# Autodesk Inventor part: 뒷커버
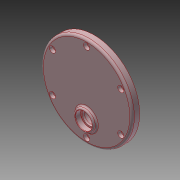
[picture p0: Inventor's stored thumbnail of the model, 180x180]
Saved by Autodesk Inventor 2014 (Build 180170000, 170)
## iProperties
Created: 2024-02
Part Number: 뒷커버
Material: 알루미늄 6061
Document SubType Name: Modeling
Designer: mdu-01
Density: 2.71 g/cm^3
Mass: 304.885 g
Surface Area: 294.624 cm^2
Volume: 112.504 cm^3
Appearance: 기본값(1)
Author: mdu-01
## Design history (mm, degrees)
sketch "스케치1"
  geometry: C1 r 60 at (0, 0) reference; C2 r 44 at (0, 0) reference; C3 r 11 at (0, -31) reference; C4 r 11 at (0, 0) reference; C5 r 46 at (0, 0) reference; A1 r 41 centre (0, 0) between (20.39, -35.57) and (-20.39, -35.57); A2 r 16 centre (0, 0) between (9.254, -13.053) and (-9.254, -13.053); A3 r 16 centre (0, -31) between (15.914, -32.657) and (9.254, -17.947); A4 r 16 centre (0, -31) between (-9.254, -17.947) and (-15.914, -32.657); A5 r 3 centre (18.898, -32.968) between (15.914, -32.657) and (20.39, -35.57); A6 r 3 centre (-18.898, -32.968) between (-20.39, -35.57) and (-15.914, -32.657); A7 r 3 centre (-10.989, -15.5) between (-9.254, -17.947) and (-9.254, -13.053); A8 r 3 centre (10.989, -15.5) between (9.254, -13.053) and (9.254, -17.947); 1 further point
  constraints: 16 point on circle, 8 centre point, 8 tangent, 5 equal radius
  dimensions: "d2" = 5 radial gap between concentric circles of C4 A2; "d3" = 3 radius of A5; "d46" = 5 radial gap between concentric circles of C5 A1
  node "참조1"
  node "참조2"
  node "참조3"
  node "참조4"
  node "참조11"
extrude "돌출1" new body sketch "스케치1" distance "d4" = 10; taper "d5" = 0 deg
extrude "돌출2" join sketch "스케치1" distance "d6" = 3; taper "d7" = 0 deg
chamfer "모따기1" distance "d8" = 1; stored, may be unused: second distance "d9" = 2, angle "d10" = 45 deg
sketch "스케치2"
  geometry: C1 r 13.5 at (0, -31); A1 r 3.5 centre (0, -31) between (1, -34.354) and (-1, -34.354) reference; 1 further point
  constraints: 1 centre point
  dimensions: "d11" = 27 diameter of C1
extrude "돌출3" join sketch "스케치2" distance "d14" = 4; taper "d15" = 0 deg
fillet "모깎기1" dims "d16" = 3
sketch "스케치3"
  geometry: C1 r 1.621 at (0, 52) reference; 1 further point
hole "구멍1" sketch "스케치3" at (0, 52) diameter "d18" = 4.5; stored, may be unused: countersink angle "d22" = 90 deg, drill point angle "d24" = 118 deg; dims "d19" = 6, "d20" = 8, "d21" = 4.4, "d23" = 8
fillet "모깎기2" dims "d31" = 2
sketch "스케치4"
  geometry: L1 (11, 3.7)-(11, -2.7) reference; L2 (-10.7, 4)-(10.7, 4) reference; L3 (10.7, -3)-(-10.7, -3) reference; L4 (10.7, -3)-(11, -3); L5 (11, -3)-(11, -2.7); L6 (6, 7)-(0, 7); L7 (0, 7)-(0, -3); L8 (10.7, 4)-(9, 4); A1 r 0.3 centre (10.7, 3.7) between (11, 3.7) and (10.7, 4); A2 r 3 centre (6, 4) between (9, 4) and (6, 7); 1 further point
  constraints: 13 end point, 4 point on circle, 3 tangent, 2 centre point, 2 collinear, 2 perpendicular, 2 point on line, 1 midpoint, 1 vertical, 2 other
  dimensions: "d33" = 3 distance from line of L6.start L2; "d34" = 2 distance from line of L8.end L1
revolve "회전1" sketch "스케치4" stored, may be unused: angle "d35" = 90 deg
sketch "스케치5"
  geometry: L1 (-20.3, -3)-(-41.7, -3) reference; L2 (-20, 3.7)-(-20, -2.7) reference; L3 (-41.7, 4)-(-20.3, 4) reference; L4 (-42.5, 14)-(-19.5, 14) reference; L5 (-20.3, -3)-(-20, -3); L6 (-20, -3)-(-20, -2.7); L7 (-20.3, 4)-(-22, 4); L8 (-20, 13.3)-(-20, 7); L9 (-20.3, 6.7)-(-22, 6.7); L10 (-22, 6.7)-(-22, 4); L11 (-19.596, 14)-(-20, 13.3); L12 (-31, -3)-(-31, 14); A1 r 0.3 centre (-20.3, 3.7) between (-20, 3.7) and (-20.3, 4); A2 r 0.3 centre (-20.3, 7) between (-20.3, 6.7) and (-20, 7); 1 further point
  constraints: 18 end point, 4 point on circle, 3 perpendicular, 3 tangent, 2 centre point, 2 midpoint, 2 parallel, 2 point on line, 1 vertical, 2 other
  dimensions: "d36" = 7.3 distance between parallel lines of L9 L4; "d37" = 2 distance between parallel lines of L2 L10; "d38" = 0.7 distance from line of L8.start L4; "d39" = 30 deg angle of L8 L11; "d40" = 22 diameter of L8 L12; "d41" = 0.3 radius of A2
revolve "회전2" sketch "스케치5" stored, may be unused: angle "d42" = 90 deg
chamfer "모따기2" distance "d43" = 0.5; stored, may be unused: second distance "d44" = 2, angle "d45" = 45 deg
node "솔리드1"
pattern_circular "원형 패턴1" dims angle "d26" = 360 deg
node "참조5"
node "참조6"
node "참조7"
node "참조8"
node "참조9"
node "참조10"
other parameters: "d1" = 5
